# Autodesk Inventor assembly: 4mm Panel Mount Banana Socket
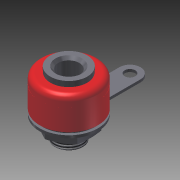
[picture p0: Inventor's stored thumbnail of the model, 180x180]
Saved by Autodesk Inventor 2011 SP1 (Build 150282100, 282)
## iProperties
Created: 2011-10
Part Number: 4mm Panel Mount Banana Socket
Document SubType Name: Assembly
Designer: sdarley
Author: sdarley
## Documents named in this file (7)
- C:\Users\sdarley\Documents\Inventor\FatigueTestJig\4mm Panel Mount Banana Socket\4mm Panel Mount Banana Socket.iam
- C:\Users\sdarley\Documents\Inventor\FatigueTestJig\4mm Panel Mount Banana Socket\Components\Plastic Cap.ipt
- C:\Users\sdarley\Documents\Inventor\FatigueTestJig\4mm Panel Mount Banana Socket\Components\Plastic Cap top.ipt
- C:\Users\sdarley\Documents\Inventor\FatigueTestJig\4mm Panel Mount Banana Socket\Components\Socket Tube.ipt
- C:\Users\sdarley\Documents\Inventor\FatigueTestJig\4mm Panel Mount Banana Socket\Components\Wire Connector.ipt
- C:\Users\sdarley\Documents\Inventor\FatigueTestJig\4mm Panel Mount Banana Socket\Components\Washer.ipt
- C:\Users\sdarley\Documents\Inventor\FatigueTestJig\4mm Panel Mount Banana Socket\Components\Connector Nut.ipt
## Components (6 placed, 6 different names)
1. Plastic Cap:1 — Flush:1
2. Plastic Cap top:1 — Flush:1, Flush:2, Flush:3
3. Socket Tube:1 — Flush:2
4. Wire Connector:1 — Flush:3, Flush:4
5. Washer:1 — Flush:4, Flush:5
6. Connector Nut:1 — Flush:5
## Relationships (5: Flush 5)
- Flush:1: Plastic Cap:1 ↔ Plastic Cap top:1
- Flush:2: Plastic Cap top:1 ↔ Socket Tube:1
- Flush:3: Plastic Cap top:1 ↔ Wire Connector:1
- Flush:4: Wire Connector:1 ↔ Washer:1
- Flush:5: Washer:1 ↔ Connector Nut:1
